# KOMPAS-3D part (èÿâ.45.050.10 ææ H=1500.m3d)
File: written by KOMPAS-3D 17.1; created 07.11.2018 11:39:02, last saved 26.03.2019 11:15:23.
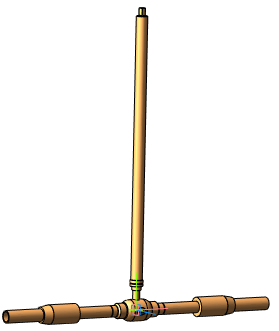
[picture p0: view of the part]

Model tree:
1. Операция без истории:2  (labels: Сталь 20  ГОСТ 1050-2013)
